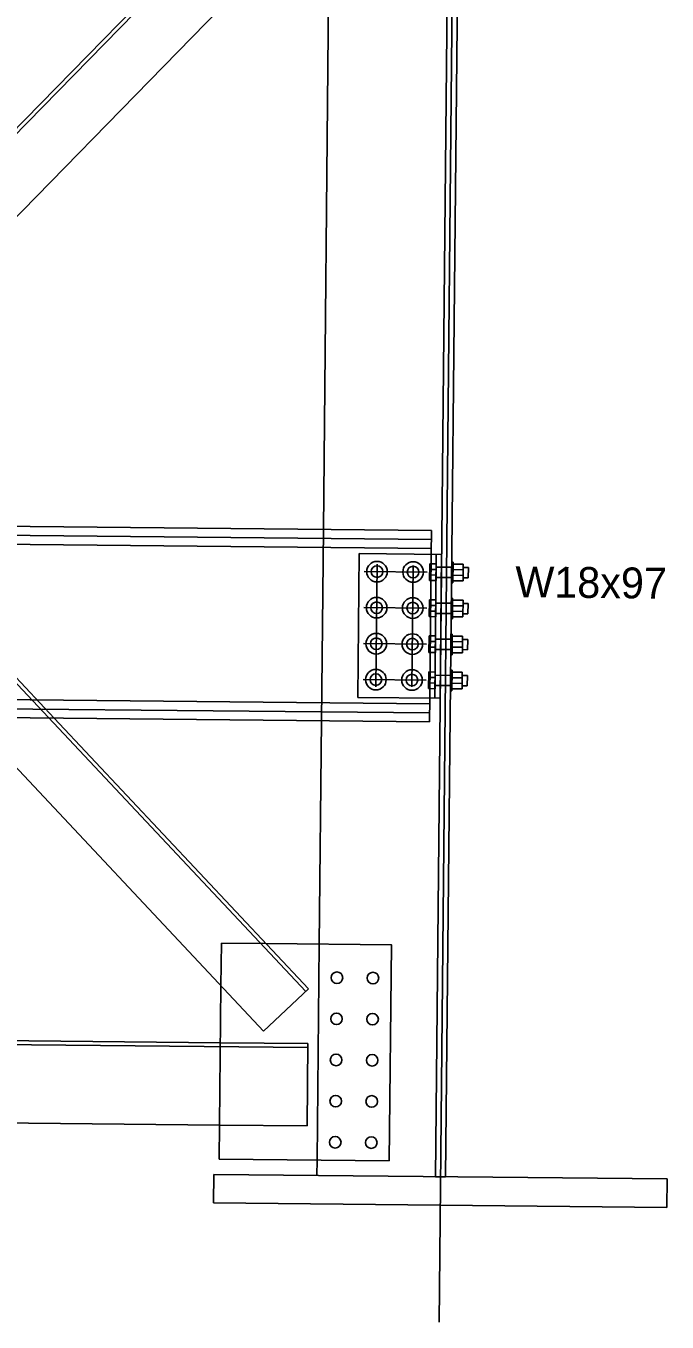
# Model space of a CAD drawing. Extents: x 632312 to 632885, y 378199 to 378534.
# Drawn here: x 632536.24 to 632541.43, y 378438.97 to 378449.47 of the extents above; entities that cross this region are included whole.
import ezdxf

# ---------------------------------------------------------------- set-up
doc = ezdxf.new("R2010")
doc.units = 0
for name, color, linetype in [('B_Boring', 7, 'Continuous'), ('R_Proposed Const Limits Cut', 7, 'Continuous'), ('R_Shade Removal', 7, 'Continuous'), ('R_Wall', 7, 'Continuous'), ('SHT_Dimensions', 7, 'Continuous')]:
    doc.layers.add(name, color=color, linetype=linetype)

msp = doc.modelspace()

# ---------------------------------------------------------------- linework, layer by layer
at = {"layer": 'B_Boring'}
for p, q in [((632538.645, 378445.387), (632538.691, 378450.071)), ((632539.52, 378445.379), (632528.52, 378445.488)), ((632539.519, 378445.306), (632528.52, 378445.416)), ((632539.518, 378445.187), (632539.52, 378445.379)), ((632538.935, 378445.193), (632538.923, 378444.026)), ((632539.601, 378445.186), (632538.935, 378445.193)), ((632539.548, 378444.02), (632539.559, 378445.187)), ((632539.601, 378445.186), (632539.59, 378444.02)), ((632539.507, 378445.109), (632539.505, 378444.974)), ((632539.558, 378445.063), (632539.506, 378445.064)), ((632539.559, 378445.108), (632539.507, 378445.109)), ((632539.6, 378445.082), (632539.683, 378445.081)), ((632539.682, 378444.956), (632539.684, 378445.123)), ((632539.684, 378445.123), (632539.694, 378445.123)), ((632539.694, 378445.123), (632539.693, 378444.956)), ((632539.694, 378445.107), (632539.777, 378445.106)), ((632539.694, 378445.062), (632539.777, 378445.061)), ((632539.777, 378445.106), (632539.776, 378444.971)), ((632539.777, 378445.08), (632539.819, 378445.08)), ((632539.819, 378445.08), (632539.818, 378444.997)), ((632539.557, 378444.973), (632539.505, 378444.974)), ((632539.558, 378445.018), (632539.506, 378445.019)), ((632539.599, 378444.999), (632539.683, 378444.998)), ((632539.682, 378444.956), (632539.693, 378444.956)), ((632539.693, 378445.017), (632539.777, 378445.016)), ((632539.693, 378444.972), (632539.776, 378444.971)), ((632539.776, 378444.997), (632539.818, 378444.997)), ((632539.504, 378444.817), (632539.502, 378444.682)), ((632539.555, 378444.772), (632539.503, 378444.772)), ((632539.556, 378444.817), (632539.504, 378444.817)), ((632539.679, 378444.665), (632539.681, 378444.831)), ((632539.681, 378444.831), (632539.691, 378444.831)), ((632539.691, 378444.831), (632539.69, 378444.664)), ((632539.691, 378444.815), (632539.775, 378444.815)), ((632539.691, 378444.77), (632539.774, 378444.769)), ((632539.775, 378444.815), (632539.773, 378444.679)), ((632539.774, 378444.789), (632539.816, 378444.788)), ((632539.816, 378444.788), (632539.815, 378444.705)), ((632539.554, 378444.681), (632539.502, 378444.682)), ((632539.555, 378444.727), (632539.503, 378444.727)), ((632539.679, 378444.665), (632539.69, 378444.664)), ((632539.69, 378444.725), (632539.774, 378444.724)), ((632539.69, 378444.68), (632539.773, 378444.679)), ((632539.773, 378444.705), (632539.815, 378444.705)), ((632539.501, 378444.526), (632539.499, 378444.39)), ((632539.553, 378444.525), (632539.501, 378444.526)), ((632539.676, 378444.373), (632539.678, 378444.54)), ((632539.678, 378444.54), (632539.688, 378444.539)), ((632539.688, 378444.539), (632539.687, 378444.373)), ((632539.688, 378444.524), (632539.772, 378444.523)), ((632539.772, 378444.523), (632539.77, 378444.388)), ((632539.552, 378444.48), (632539.5, 378444.481)), ((632539.552, 378444.435), (632539.5, 378444.435)), ((632539.687, 378444.434), (632539.771, 378444.433)), ((632539.688, 378444.479), (632539.771, 378444.478)), ((632539.771, 378444.497), (632539.813, 378444.497)), ((632539.813, 378444.497), (632539.812, 378444.413)), ((632539.552, 378444.39), (632539.499, 378444.39)), ((632539.676, 378444.373), (632539.687, 378444.373)), ((632539.687, 378444.388), (632539.77, 378444.388)), ((632539.771, 378444.414), (632539.812, 378444.413)), ((632539.498, 378444.234), (632539.497, 378444.099)), ((632539.55, 378444.233), (632539.498, 378444.234)), ((632539.674, 378444.081), (632539.675, 378444.248)), ((632539.675, 378444.248), (632539.686, 378444.248)), ((632539.686, 378444.248), (632539.684, 378444.081)), ((632539.685, 378444.232), (632539.769, 378444.231)), ((632539.769, 378444.231), (632539.767, 378444.096)), ((632539.55, 378444.188), (632539.497, 378444.189)), ((632539.549, 378444.143), (632539.497, 378444.144)), ((632539.685, 378444.187), (632539.768, 378444.186)), ((632539.685, 378444.142), (632539.768, 378444.141)), ((632539.768, 378444.205), (632539.81, 378444.205)), ((632539.768, 378444.122), (632539.809, 378444.122)), ((632539.81, 378444.205), (632539.809, 378444.122)), ((632539.505, 378443.901), (632528.506, 378444.011)), ((632538.923, 378444.026), (632539.59, 378444.02)), ((632539.549, 378444.098), (632539.497, 378444.099)), ((632539.504, 378443.829), (632539.506, 378444.02)), ((632539.674, 378444.081), (632539.684, 378444.081)), ((632539.684, 378444.097), (632539.767, 378444.096)), ((632539.504, 378443.829), (632528.505, 378443.938)), ((632538.611, 378442.03), (632538.629, 378443.837)), ((632538.524, 378441.667), (632538.16, 378441.325)), ((632537.812, 378441.23), (632533.979, 378441.268)), ((632533.972, 378440.602), (632537.805, 378440.563)), ((632538.593, 378440.155), (632538.594, 378440.28))]:
    msp.add_line(p, q, dxfattribs=at)
for points in [[(632539.634, 378440.144), (632539.551, 378440.145), (632539.67, 378452.145), (632539.754, 378452.144)], [(632541.426, 378440.127), (632541.424, 378439.897), (632537.757, 378439.934), (632537.759, 378440.163)]]:
    msp.add_lwpolyline(points, close=True, dxfattribs=at)
for points in [[(632534.834, 378446.563), (632538.612, 378450.431), (632538.254, 378450.78), (632534.839, 378447.284)], [(632538.16, 378441.325), (632535.775, 378443.866)], [(632536.467, 378443.859), (632538.524, 378441.667)], [(632537.816, 378441.691), (632537.802, 378440.288), (632537.802, 378440.288), (632537.802, 378440.288), (632539.177, 378440.274), (632539.195, 378442.024), (632538.18, 378442.034)]]:
    msp.add_lwpolyline(points, dxfattribs=at)
for centre in [(632539.079, 378445.046), (632539.371, 378445.043), (632539.076, 378444.754), (632539.368, 378444.751), (632539.073, 378444.462), (632539.365, 378444.459), (632539.07, 378444.171), (632539.362, 378444.168), (632538.755, 378441.757), (632539.046, 378441.754), (632538.751, 378441.424), (632539.043, 378441.421), (632538.748, 378441.091), (632539.04, 378441.088), (632538.745, 378440.757), (632539.036, 378440.755), (632538.741, 378440.424), (632539.033, 378440.421)]:
    msp.add_circle(centre, 0.0469, dxfattribs=at)
at = {"layer": 'R_Proposed Const Limits Cut'}
for p, q in [((632529.87, 378450.842), (632538.502, 378441.646)), ((632538.276, 378450.758), (632529.464, 378441.735)), ((632534.999, 378445.424), (632536.467, 378443.859)), ((632538.645, 378445.387), (632538.629, 378443.837)), ((632539.518, 378445.233), (632528.519, 378445.342)), ((632539.518, 378445.187), (632539.506, 378444.02)), ((632539.558, 378445.082), (632539.6, 378445.082)), ((632539.558, 378444.999), (632539.599, 378444.999)), ((632539.556, 378444.791), (632539.681, 378444.79)), ((632539.555, 378444.707), (632539.68, 378444.706)), ((632539.553, 378444.499), (632539.678, 378444.498)), ((632539.552, 378444.416), (632539.677, 378444.415)), ((632539.549, 378444.124), (632539.674, 378444.123)), ((632539.55, 378444.207), (632539.675, 378444.206)), ((632539.506, 378443.975), (632528.506, 378444.084)), ((632537.816, 378441.691), (632537.82, 378442.038)), ((632538.18, 378442.034), (632537.82, 378442.038)), ((632538.611, 378442.03), (632538.594, 378440.28)), ((632538.52, 378441.192), (632529.437, 378441.282)), ((632538.52, 378441.223), (632537.812, 378441.23)), ((632538.513, 378440.556), (632538.52, 378441.223)), ((632537.805, 378440.563), (632538.513, 378440.556))]:
    msp.add_line(p, q, dxfattribs=at)
for centre in [(632539.079, 378445.046), (632539.371, 378445.043), (632539.076, 378444.754), (632539.368, 378444.751), (632539.073, 378444.462), (632539.365, 378444.459), (632539.07, 378444.171), (632539.362, 378444.168)]:
    msp.add_circle(centre, 0.0833, dxfattribs=at)
at = {"layer": 'R_Shade Removal'}
msp.add_line((632539.581, 378438.968), (632539.731, 378454.033), dxfattribs=at)
at = {"layer": 'R_Wall'}
for p, q in [((632539.079, 378445.106), (632539.07, 378444.113)), ((632539.371, 378445.097), (632539.361, 378444.112)), ((632538.975, 378445.047), (632539.485, 378445.041)), ((632538.972, 378444.755), (632539.482, 378444.75)), ((632538.969, 378444.463), (632539.479, 378444.458)), ((632538.966, 378444.172), (632539.476, 378444.167))]:
    msp.add_line(p, q, dxfattribs=at)
at = {"layer": 'SHT_Dimensions'}
for p, q in [((632539.559, 378445.108), (632539.557, 378444.973)), ((632539.556, 378444.817), (632539.554, 378444.681)), ((632539.553, 378444.525), (632539.552, 378444.39)), ((632539.55, 378444.233), (632539.549, 378444.098))]:
    msp.add_line(p, q, dxfattribs=at)

# ---------------------------------------------------------------- texts
msp.add_text('W18x97', height=0.25, rotation=359.4304, dxfattribs=at).set_placement((632540.197, 378444.839))

doc.saveas('drawing.dxf')
